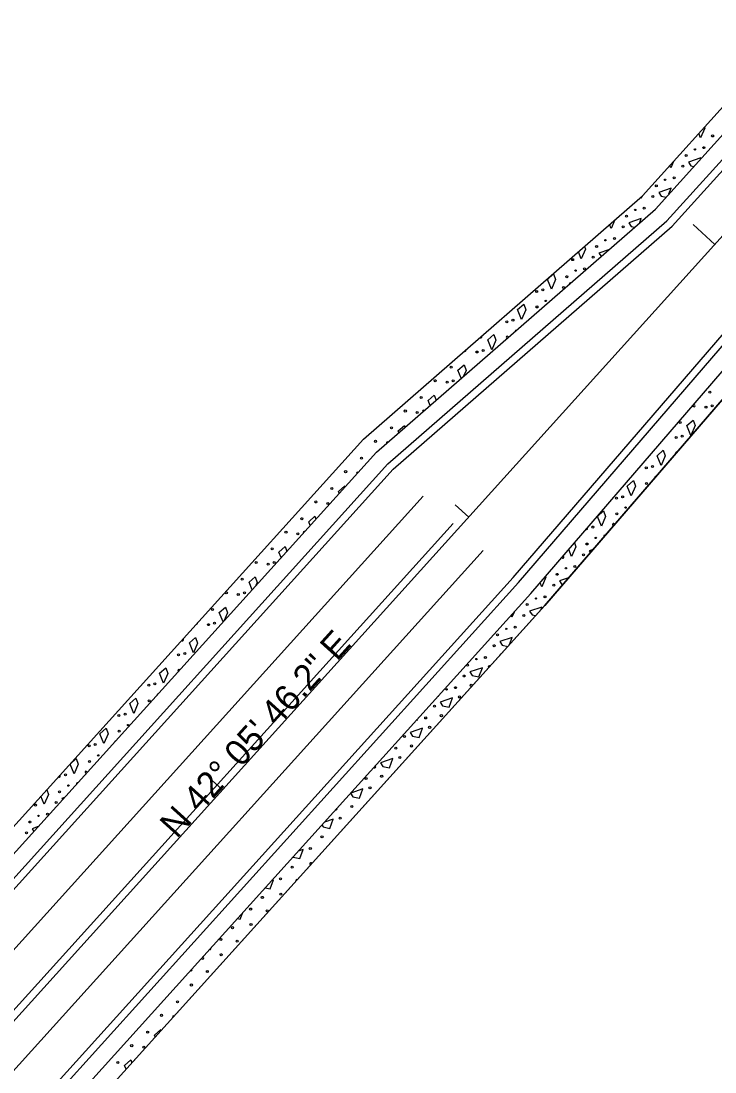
# Model space of a CAD drawing. Extents: x 1262642 to 1268358, y 767825 to 773481.
# Drawn here: x 1267038.7 to 1267227.6, y 772434 to 772720 of the extents above; entities that cross this region are included whole.
import ezdxf

# ---------------------------------------------------------------- set-up
doc = ezdxf.new("R2010")
doc.units = 0
for name, color, linetype in [('Prop Conc 2ft 6in Curb and Gutter', 7, 'Continuous'), ('Prop Conc 4in Sidewalk', 7, 'Continuous'), ('Prop EOT', 7, 'Continuous'), ('Prop Horizontal Alignment', 7, 'Continuous'), ('Prop Horizontal Alignment Direction Label', 7, 'Continuous'), ('Prop Horizontal Alignment Tick Large', 7, 'Continuous'), ('Prop Horizontal Alignment Tick Small', 7, 'Continuous'), ('Prop Lane Lines', 7, 'Continuous')]:
    doc.layers.add(name, color=color, linetype=linetype)

msp = doc.modelspace()

# ---------------------------------------------------------------- linework, layer by layer
at = {"layer": 'Prop Conc 2ft 6in Curb and Gutter'}
for p, q in [((1267207.89, 772672.41), (1267369.32, 772851.1)), ((1267211.4, 772668.84), (1267373.01, 772847.72)), ((1267214.55, 772665.62), (1267376.32, 772844.68)), ((1267174.18, 772567.23), (1267397.12, 772825.93)), ((1267177.49, 772564.18), (1267400.47, 772822.93)), ((1267404.22, 772819.62), (1267181.29, 772560.93)), ((1267224.85, 772690.88), (1267223.72, 772688.24)), ((1267224.78, 772691.11), (1267224.85, 772690.88)), ((1267223.72, 772688.24), (1267223.25, 772689.42)), ((1267216.37, 772681.8), (1267215.6, 772680)), ((1267223.8, 772682.73), (1267220.43, 772681.59)), ((1267220.43, 772681.59), (1267221.07, 772680.6)), ((1267223.7, 772682.45), (1267223.8, 772682.73)), ((1267215.6, 772680), (1267215.33, 772680.65)), ((1267221.07, 772680.6), (1267221.87, 772680.44)), ((1267215.67, 772674.48), (1267212.31, 772673.34)), ((1267212.31, 772673.34), (1267212.95, 772672.36)), ((1267215.11, 772672.95), (1267215.67, 772674.48)), ((1267131.94, 772606.25), (1267207.89, 772672.41)), ((1267207.48, 772671.75), (1267207.39, 772671.98)), ((1267207.68, 772672.23), (1267207.48, 772671.75)), ((1267212.95, 772672.36), (1267214.32, 772672.07)), ((1267135.45, 772602.68), (1267211.4, 772668.84)), ((1267138.61, 772599.46), (1267214.55, 772665.62)), ((1267199.35, 772663.51), (1267198.91, 772664.59)), ((1267200.35, 772665.85), (1267199.35, 772663.51)), ((1267207.55, 772666.24), (1267204.18, 772665.1)), ((1267204.18, 772665.1), (1267204.83, 772664.11)), ((1267204.83, 772664.11), (1267205.75, 772663.92)), ((1267207.15, 772665.14), (1267207.55, 772666.24)), ((1267192.1, 772658.66), (1267192.36, 772657.9)), ((1267191.23, 772655.26), (1267190.44, 772657.21)), ((1267192.36, 772657.9), (1267191.23, 772655.26)), ((1267198.64, 772657.73), (1267196.06, 772656.85)), ((1267196.06, 772656.85), (1267196.63, 772655.98)), ((1267182.03, 772649.7), (1267183.71, 772651.19)), ((1267183.11, 772647.02), (1267182.03, 772649.7)), ((1267184.24, 772649.66), (1267183.11, 772647.02)), ((1267183.71, 772651.19), (1267184.24, 772649.66)), ((1267188.33, 772648.74), (1267187.94, 772648.61)), ((1267187.94, 772648.61), (1267188.02, 772648.48)), ((1267173.9, 772641.45), (1267175.59, 772642.95)), ((1267174.98, 772638.77), (1267173.9, 772641.45)), ((1267176.11, 772641.42), (1267174.98, 772638.77)), ((1267175.59, 772642.95), (1267176.11, 772641.42)), ((1267165.78, 772633.21), (1267167.46, 772634.71)), ((1267166.86, 772630.53), (1267165.78, 772633.21)), ((1267167.99, 772633.17), (1267166.86, 772630.53)), ((1267167.46, 772634.71), (1267167.99, 772633.17)), ((1267157.66, 772624.96), (1267159.34, 772626.46)), ((1267158.53, 772622.79), (1267157.66, 772624.96)), ((1267159.87, 772624.93), (1267159.2, 772623.37)), ((1267159.34, 772626.46), (1267159.87, 772624.93)), ((1267149.53, 772616.72), (1267151.22, 772618.22)), ((1267151.22, 772618.22), (1267151.69, 772616.83)), ((1267150.06, 772615.41), (1267149.53, 772616.72)), ((1267141.41, 772608.48), (1267143.1, 772609.97)), ((1267143.1, 772609.97), (1267143.26, 772609.48)), ((1267220, 772609.93), (1267221.69, 772611.42)), ((1267221.09, 772607.25), (1267220, 772609.93)), ((1267222.21, 772609.89), (1267221.09, 772607.25)), ((1267221.69, 772611.42), (1267222.21, 772609.89)), ((1267141.59, 772608.03), (1267141.41, 772608.48)), ((1267131.94, 772606.25), (1266835.45, 772278.08)), ((1267135.45, 772602.68), (1266839.16, 772274.72)), ((1267211.88, 772601.68), (1267213.57, 772603.18)), ((1267212.96, 772599), (1267211.88, 772601.68)), ((1267214.09, 772601.64), (1267212.96, 772599)), ((1267213.57, 772603.18), (1267214.09, 772601.64)), ((1267138.61, 772599.46), (1266842.5, 772271.71)), ((1267125.16, 772591.99), (1267126.85, 772593.48)), ((1267126.85, 772593.48), (1267126.93, 772593.25)), ((1267203.76, 772593.44), (1267205.44, 772594.93)), ((1267204.84, 772590.76), (1267203.76, 772593.44)), ((1267205.97, 772593.4), (1267204.84, 772590.76)), ((1267205.44, 772594.93), (1267205.97, 772593.4)), ((1267125.36, 772591.5), (1267125.16, 772591.99)), ((1267195.64, 772585.19), (1267197.32, 772586.69)), ((1267197.32, 772586.69), (1267197.85, 772585.16)), ((1267117.04, 772583.74), (1267118.73, 772585.24)), ((1267118.73, 772585.24), (1267118.99, 772584.46)), ((1267196.72, 772582.51), (1267195.64, 772585.19)), ((1267197.85, 772585.16), (1267196.72, 772582.51)), ((1267117.44, 772582.74), (1267117.04, 772583.74)), ((1267108.92, 772575.5), (1267110.6, 772577)), ((1267109.53, 772573.98), (1267108.92, 772575.5)), ((1267110.6, 772577), (1267111.05, 772575.67)), ((1267188.59, 772574.27), (1267187.82, 772576.17)), ((1267189.72, 772576.91), (1267188.59, 772574.27)), ((1267189.36, 772577.96), (1267189.72, 772576.91)), ((1267194.46, 772576.21), (1267193.42, 772575.86)), ((1267193.42, 772575.86), (1267193.74, 772575.38)), ((1267174.15, 772567.2), (1266880.18, 772241.82)), ((1267100.79, 772567.25), (1267102.48, 772568.75)), ((1267101.61, 772565.22), (1267100.79, 772567.25)), ((1267102.48, 772568.75), (1267103, 772567.22)), ((1267103, 772567.22), (1267102.63, 772566.35)), ((1267180.47, 772566.02), (1267180.03, 772567.12)), ((1267181.6, 772568.67), (1267180.47, 772566.02)), ((1267181.53, 772568.87), (1267181.6, 772568.67)), ((1267187.77, 772568.45), (1267185.3, 772567.62)), ((1267185.3, 772567.62), (1267185.94, 772566.63)), ((1267185.94, 772566.63), (1267186.16, 772566.59)), ((1266883.52, 772238.8), (1267177.49, 772564.18)), ((1267181.29, 772560.93), (1266887.23, 772235.45)), ((1267092.67, 772559.01), (1267094.36, 772560.51)), ((1267093.7, 772556.46), (1267092.67, 772559.01)), ((1267094.88, 772558.97), (1267093.9, 772556.69)), ((1267094.36, 772560.51), (1267094.88, 772558.97)), ((1267172.35, 772557.78), (1267172.15, 772558.27)), ((1267172.92, 772559.12), (1267172.35, 772557.78)), ((1267180.54, 772560.51), (1267177.18, 772559.37)), ((1267177.18, 772559.37), (1267177.82, 772558.39)), ((1267177.82, 772558.39), (1267178.81, 772558.18)), ((1267180.29, 772559.83), (1267180.54, 772560.51)), ((1267084.55, 772550.76), (1267086.23, 772552.26)), ((1267085.63, 772548.09), (1267084.55, 772550.76)), ((1267086.76, 772550.73), (1267085.63, 772548.09)), ((1267086.23, 772552.26), (1267086.76, 772550.73)), ((1267172.42, 772552.27), (1267169.05, 772551.13)), ((1267169.05, 772551.13), (1267169.7, 772550.14)), ((1267169.7, 772550.14), (1267171.25, 772549.82)), ((1267171.71, 772550.32), (1267172.42, 772552.27)), ((1267076.42, 772542.52), (1267078.11, 772544.02)), ((1267078.11, 772544.02), (1267078.63, 772542.48)), ((1267164.3, 772544.02), (1267160.93, 772542.88)), ((1267163.38, 772541.52), (1267164.3, 772544.02)), ((1267077.5, 772539.84), (1267076.42, 772542.52)), ((1267078.63, 772542.48), (1267077.5, 772539.84)), ((1267160.93, 772542.88), (1267161.57, 772541.9)), ((1267161.57, 772541.9), (1267163.38, 772541.52)), ((1267068.3, 772534.28), (1267069.99, 772535.77)), ((1267069.99, 772535.77), (1267070.51, 772534.24)), ((1267156.17, 772535.78), (1267152.81, 772534.64)), ((1267155.26, 772533.28), (1267156.17, 772535.78)), ((1267069.38, 772531.6), (1267068.3, 772534.28)), ((1267070.51, 772534.24), (1267069.38, 772531.6)), ((1267152.81, 772534.64), (1267153.45, 772533.65)), ((1267153.45, 772533.65), (1267155.26, 772533.28)), ((1267060.18, 772526.03), (1267061.86, 772527.53)), ((1267061.86, 772527.53), (1267062.39, 772525.99)), ((1267148.05, 772527.53), (1267144.68, 772526.4)), ((1267147.13, 772525.03), (1267148.05, 772527.53)), ((1267061.26, 772523.35), (1267060.18, 772526.03)), ((1267062.39, 772525.99), (1267061.26, 772523.35)), ((1267144.68, 772526.4), (1267145.33, 772525.41)), ((1267145.33, 772525.41), (1267147.13, 772525.03)), ((1267052.05, 772517.79), (1267053.74, 772519.28)), ((1267053.74, 772519.28), (1267054.26, 772517.75)), ((1267139.93, 772519.29), (1267136.56, 772518.15)), ((1267136.56, 772518.15), (1267137.2, 772517.17)), ((1267139.01, 772516.79), (1267139.93, 772519.29)), ((1267053.13, 772515.11), (1267052.05, 772517.79)), ((1267054.26, 772517.75), (1267053.13, 772515.11)), ((1267137.2, 772517.17), (1267139.01, 772516.79)), ((1267046.14, 772509.51), (1267045.01, 772506.86)), ((1267045.7, 772510.79), (1267046.14, 772509.51)), ((1267128.44, 772509.9), (1267129.08, 772508.92)), ((1267131.8, 772511.05), (1267128.46, 772509.92)), ((1267130.89, 772508.55), (1267131.8, 772511.05)), ((1267045.01, 772506.86), (1267044.13, 772509.05)), ((1267050.54, 772508.69), (1267049.84, 772508.46)), ((1267049.84, 772508.46), (1267050.05, 772508.14)), ((1267129.08, 772508.92), (1267130.89, 772508.55)), ((1267120.6, 772501.22), (1267120.96, 772500.68)), ((1267123.68, 772502.8), (1267121.31, 772502)), ((1267122.76, 772500.3), (1267123.68, 772502.8)), ((1267043.39, 772500.78), (1267041.72, 772500.21)), ((1267041.72, 772500.21), (1267042.21, 772499.47)), ((1267120.96, 772500.68), (1267122.76, 772500.3)), ((1267112.76, 772492.54), (1267112.83, 772492.43)), ((1267112.83, 772492.43), (1267114.64, 772492.06)), ((1267115.56, 772494.56), (1267114.16, 772494.08)), ((1267114.64, 772492.06), (1267115.56, 772494.56)), ((1267105.14, 772484.1), (1267106.52, 772483.81)), ((1267106.52, 772483.81), (1267107.44, 772486.31)), ((1267107.44, 772486.31), (1267107.01, 772486.17)), ((1267097.58, 772475.74), (1267098.39, 772475.57)), ((1267098.39, 772475.57), (1267099.05, 772477.36)), ((1267090.03, 772467.37), (1267090.27, 772467.32)), ((1267090.27, 772467.32), (1267090.47, 772467.86)), ((1267075.05, 772444.04), (1267076.73, 772445.53)), ((1267075.24, 772443.55), (1267075.05, 772444.04)), ((1267076.73, 772445.53), (1267076.82, 772445.29)), ((1267066.92, 772435.79), (1267068.61, 772437.29)), ((1267067.33, 772434.79), (1267066.92, 772435.79)), ((1267068.61, 772437.29), (1267068.88, 772436.5))]:
    msp.add_line(p, q, dxfattribs=at)
for centre, radius in [((1267227, 772688.71), 0.268), ((1267222.18, 772685.06), 0.18), ((1267224.62, 772685.53), 0.268), ((1267219.79, 772683.4), 0.268), ((1267218.87, 772680.47), 0.268), ((1267211.67, 772675.16), 0.268), ((1267214.06, 772676.82), 0.18), ((1267216.49, 772677.29), 0.268), ((1267210.75, 772672.22), 0.268), ((1267203.55, 772666.91), 0.268), ((1267205.94, 772668.57), 0.18), ((1267208.37, 772669.05), 0.268), ((1267202.63, 772663.98), 0.268), ((1267200.25, 772660.8), 0.268), ((1267195.42, 772658.67), 0.268), ((1267197.81, 772660.33), 0.18), ((1267188.89, 772655.05), 0.268), ((1267194.5, 772655.73), 0.268), ((1267192.13, 772652.56), 0.268), ((1267187.3, 772650.42), 0.268), ((1267189.69, 772652.08), 0.18), ((1267179.09, 772646.42), 0.268), ((1267180.76, 772646.81), 0.268), ((1267186.38, 772647.49), 0.268), ((1267181.57, 772643.84), 0.18), ((1267179.18, 772642.18), 0.268), ((1267170.96, 772638.17), 0.268), ((1267172.64, 772638.56), 0.268), ((1267162.84, 772629.93), 0.268), ((1267164.52, 772630.32), 0.268), ((1267155.79, 772625.79), 0.268), ((1267151.45, 772622.11), 0.289), ((1267154.72, 772621.69), 0.268), ((1267156.39, 772622.07), 0.268), ((1267226.27, 772619), 0.268), ((1267147.67, 772617.55), 0.268), ((1267226.87, 772615.28), 0.268), ((1267143.32, 772613.86), 0.289), ((1267146.59, 772613.44), 0.268), ((1267225.19, 772614.89), 0.268), ((1267139.55, 772609.3), 0.268), ((1267218.14, 772610.76), 0.268), ((1267217.07, 772606.65), 0.268), ((1267218.74, 772607.04), 0.268), ((1267135.2, 772605.62), 0.289), ((1267131.42, 772601.06), 0.268), ((1267208.94, 772598.4), 0.268), ((1267210.62, 772598.79), 0.268), ((1267127.08, 772597.37), 0.289), ((1267123.3, 772592.82), 0.268), ((1267209.03, 772594.16), 0.268), ((1267200.82, 772590.16), 0.268), ((1267202.5, 772590.55), 0.268), ((1267118.95, 772589.13), 0.289), ((1267122.23, 772588.71), 0.268), ((1267203.3, 772587.58), 0.18), ((1267115.18, 772584.57), 0.268), ((1267200.91, 772585.92), 0.268), ((1267110.83, 772580.89), 0.289), ((1267194.37, 772582.3), 0.268), ((1267114.1, 772580.46), 0.268), ((1267195.18, 772579.34), 0.18), ((1267107.05, 772576.33), 0.268), ((1267192.79, 772577.68), 0.268), ((1267102.71, 772572.64), 0.289), ((1267105.98, 772572.22), 0.268), ((1267107.66, 772572.61), 0.268), ((1267191.87, 772574.74), 0.268), ((1267184.66, 772569.43), 0.268), ((1267187.05, 772571.09), 0.18), ((1267189.49, 772571.56), 0.268), ((1267098.93, 772568.08), 0.268), ((1267183.74, 772566.5), 0.268), ((1267094.59, 772564.4), 0.289), ((1267097.86, 772563.97), 0.268), ((1267099.53, 772564.36), 0.268), ((1267176.54, 772561.19), 0.268), ((1267178.93, 772562.85), 0.18), ((1267181.36, 772563.32), 0.268), ((1267090.81, 772559.84), 0.268), ((1267175.62, 772558.25), 0.268), ((1267089.73, 772555.73), 0.268), ((1267091.41, 772556.12), 0.268), ((1267173.24, 772555.07), 0.268), ((1267168.42, 772552.94), 0.268), ((1267170.81, 772554.6), 0.18), ((1267167.5, 772550.01), 0.268), ((1267081.61, 772547.49), 0.268), ((1267083.29, 772547.87), 0.268), ((1267165.12, 772546.83), 0.268), ((1267160.29, 772544.7), 0.268), ((1267162.68, 772546.36), 0.18), ((1267159.37, 772541.76), 0.268), ((1267073.49, 772539.24), 0.268), ((1267075.16, 772539.63), 0.268), ((1267154.56, 772538.11), 0.18), ((1267157, 772538.59), 0.268), ((1267161.27, 772539.22), 0.292), ((1267073.58, 772535), 0.268), ((1267158.08, 772536.05), 0.285), ((1267151.25, 772533.52), 0.268), ((1267065.36, 772531), 0.268), ((1267067.04, 772531.39), 0.268), ((1267148.87, 772530.34), 0.268), ((1267153.15, 772530.97), 0.292), ((1267065.45, 772526.76), 0.268), ((1267067.84, 772528.42), 0.18), ((1267149.95, 772527.8), 0.285), ((1267143.13, 772525.28), 0.268), ((1267057.24, 772522.75), 0.268), ((1267058.92, 772523.14), 0.268), ((1267140.75, 772522.1), 0.268), ((1267145.03, 772522.73), 0.292), ((1267057.33, 772518.51), 0.268), ((1267059.72, 772520.17), 0.18), ((1267141.83, 772519.56), 0.285), ((1267050.79, 772514.9), 0.268), ((1267132.63, 772513.85), 0.268), ((1267136.9, 772514.48), 0.292), ((1267049.21, 772510.27), 0.268), ((1267051.59, 772511.93), 0.18), ((1267133.71, 772511.32), 0.285), ((1267042.67, 772506.65), 0.268), ((1267048.28, 772507.34), 0.268), ((1267043.47, 772503.69), 0.18), ((1267045.91, 772504.16), 0.268), ((1267128.78, 772506.24), 0.292), ((1267041.08, 772502.03), 0.268), ((1267125.58, 772503.07), 0.285), ((1267040.16, 772499.09), 0.268), ((1267120.66, 772497.99), 0.292), ((1267117.46, 772494.83), 0.285), ((1267112.53, 772489.75), 0.292), ((1267109.34, 772486.58), 0.285), ((1267104.41, 772481.51), 0.292), ((1267109.45, 772482.4), 0.289), ((1267101.21, 772478.34), 0.285), ((1267105.68, 772477.84), 0.268), ((1267096.29, 772473.26), 0.292), ((1267101.33, 772474.16), 0.289), ((1267093.09, 772470.09), 0.285), ((1267097.55, 772469.6), 0.268), ((1267093.21, 772465.91), 0.289), ((1267089.43, 772461.36), 0.268), ((1267085.09, 772457.67), 0.289), ((1267081.31, 772453.11), 0.268), ((1267076.96, 772449.43), 0.289), ((1267073.18, 772444.87), 0.268), ((1267068.84, 772441.18), 0.289), ((1267072.11, 772440.76), 0.268), ((1267065.06, 772436.62), 0.268)]:
    msp.add_circle(centre, radius, dxfattribs=at)
for centre, radius, start, end in [((1267187.21, 772654.66), 0.268, 268.458, 353.6641), ((1267173.44, 772635.6), 0.18, 89.6098, 172.5123), ((1267163.92, 772634.04), 0.268, 209.8212, 52.3009), ((1267171.05, 772633.94), 0.268, 358.4188, 263.7033), ((1267159.57, 772630.35), 0.289, 225.6667, 36.4554), ((1267221.92, 772615.31), 0.289, 155.8456, 122.646), ((1267148.27, 772613.83), 0.268, 43.759, 218.3631), ((1267138.47, 772605.2), 0.268, 59.5456, 202.5765), ((1267217.16, 772602.41), 0.268, 69.3715, 209.1208), ((1267130.35, 772596.95), 0.268, 59.0068, 216.8008), ((1267211.42, 772595.82), 0.18, 64.1936, 214.2986), ((1267115.78, 772580.85), 0.268, 55.049, 220.7587), ((1267192.7, 772581.91), 0.268, 241.1761, 37.3155), ((1267199.99, 772582.99), 0.268, 348.7235, 289.7687), ((1267197.61, 772579.81), 0.268, 57.7909, 220.7013), ((1267186.25, 772574.06), 0.268, 184.4574, 21.3244), ((1267186.25, 772574.06), 0.268, 21.3244, 94.0342), ((1267086.46, 772556.15), 0.289, 262.0669, 13.7407), ((1267082.68, 772551.59), 0.268, 208.1686, 67.6391), ((1267169.4, 772547.46), 0.292, 92.4344, 183.3732), ((1267166.2, 772544.29), 0.285, 38.7964, 237.0112), ((1267081.7, 772543.25), 0.268, 38.2256, 237.5821), ((1267075.96, 772536.66), 0.18, 86.9009, 188.9068), ((1267152.17, 772536.45), 0.268, 275.6298, 0.1778), ((1267146.44, 772529.87), 0.18, 240.6973, 35.1104), ((1267064.53, 772523.83), 0.268, 109.4503, 166.3574), ((1267056.41, 772515.58), 0.268, 327.4522, 308.3554), ((1267135, 772517.03), 0.268, 210.0023, 65.8054), ((1267049.12, 772514.51), 0.268, 218.5444, 57.2632), ((1267054.03, 772512.4), 0.268, 70.1254, 205.6822), ((1267124.5, 772505.61), 0.268, 239.0686, 36.7391), ((1267117.58, 772490.65), 0.289, 14.3422, 261.4654), ((1267113.8, 772486.09), 0.268, 68.2117, 207.596), ((1267088.16, 772465.02), 0.292, 185.5485, 90.2592), ((1267084.97, 772461.85), 0.285, 238.6528, 37.1548), ((1267080.23, 772449), 0.268, 57.8089, 217.9987)]:
    msp.add_arc(centre, radius, start, end, dxfattribs=at)
at = {"layer": 'Prop Conc 4in Sidewalk'}
for p, q in [((1267207.89, 772672.41), (1267369.32, 772851.1)), ((1267211.4, 772668.84), (1267373.01, 772847.72)), ((1267177.49, 772564.18), (1267400.47, 772822.93)), ((1267181.2, 772560.83), (1267404.32, 772819.73)), ((1267131.94, 772606.25), (1267207.89, 772672.41)), ((1267135.45, 772602.68), (1267211.4, 772668.84)), ((1267131.94, 772606.25), (1266835.45, 772278.08)), ((1267135.45, 772602.68), (1266839.16, 772274.72)), ((1267177.49, 772564.18), (1266883.52, 772238.8)), ((1267181.2, 772560.83), (1266887.23, 772235.45))]:
    msp.add_line(p, q, dxfattribs=at)
at = {"layer": 'Prop EOT'}
for p, q in [((1267215.96, 772664.19), (1267377.8, 772843.33)), ((1267172.67, 772568.54), (1267395.61, 772827.24)), ((1267140.02, 772598.03), (1267215.96, 772664.19)), ((1267140.02, 772598.03), (1266843.99, 772270.37)), ((1267172.67, 772568.54), (1266878.7, 772243.16))]:
    msp.add_line(p, q, dxfattribs=at)
at = {"layer": 'Prop Horizontal Alignment'}
msp.add_line((1266770.94, 772153.71), (1267443.05, 772897.65), dxfattribs=at)
at = {"layer": 'Prop Horizontal Alignment Tick Large'}
msp.add_line((1267227.63, 772659.21), (1267221.7, 772664.58), dxfattribs=at)
at = {"layer": 'Prop Horizontal Alignment Tick Small'}
for p, q in [((1267160.59, 772585.01), (1267156.88, 772588.36)), ((1267093.56, 772510.81), (1267089.85, 772514.16))]:
    msp.add_line(p, q, dxfattribs=at)
at = {"layer": 'Prop Lane Lines'}
for p, q in [((1267148.18, 772590.66), (1266852.15, 772262.99)), ((1267156.34, 772583.29), (1266860.31, 772255.62)), ((1267164.5, 772575.91), (1266868.47, 772248.25))]:
    msp.add_line(p, q, dxfattribs=at)

# ---------------------------------------------------------------- texts
at = {"layer": 'Prop Horizontal Alignment Direction Label'}
msp.add_text('N 42%%d 05\' 46.2" E', height=7, rotation=47.9038, dxfattribs=at).set_placement((1267081.1, 772497.31))

doc.saveas('drawing.dxf')
